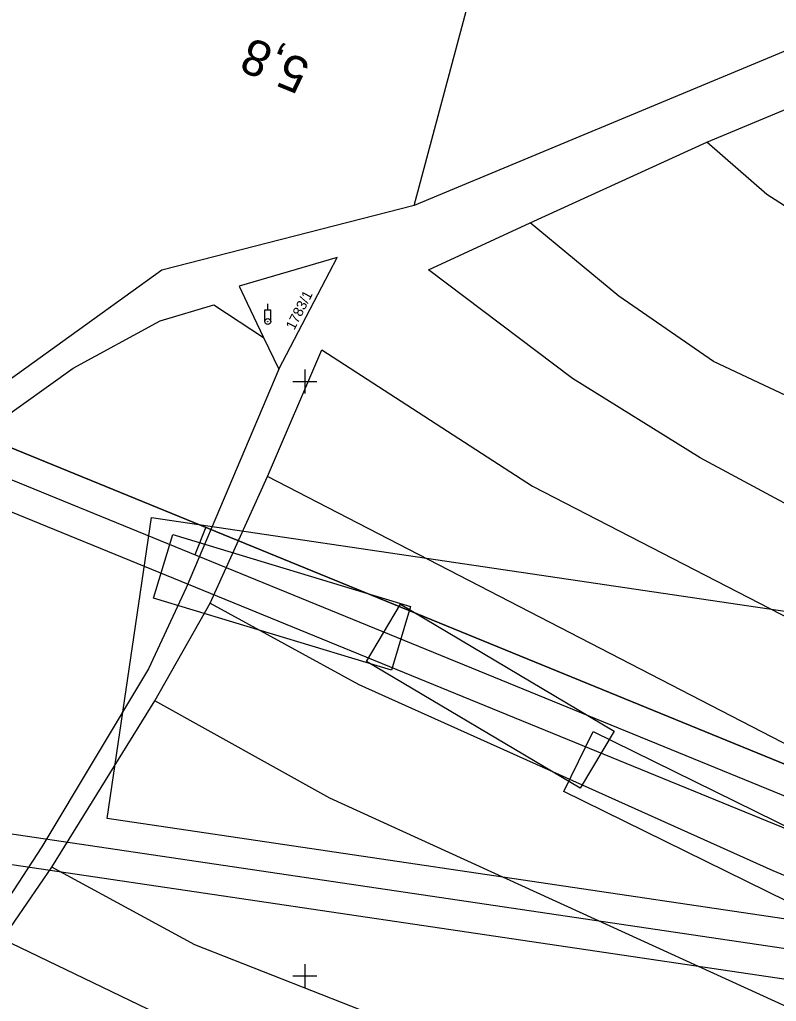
# Model space of a CAD drawing. Extents: x -779302 to -774398, y -1144902 to -1142831.
# Drawn here: x -776048 to -775920.6, y -1144504.3 to -1144339.1 of the extents above; entities that cross this region are included whole.
import ezdxf

# ---------------------------------------------------------------- set-up
doc = ezdxf.new("R2010")
doc.units = 0
for name, color, linetype in [('hektosit - Vrstva 5', 7, 'Continuous'), ('Hranice parcel', 7, 'Continuous'), ('Parcelní čísla', 7, 'Continuous'), ('Poz předměty', 7, 'Continuous'), ('Vrstva 1', 7, 'Continuous'), ('Vrstva 21', 7, 'Continuous'), ('zjednodus_g_situ-seda - Vrstva 7', 7, 'Continuous')]:
    doc.layers.add(name, color=color, linetype=linetype)

msp = doc.modelspace()

# ---------------------------------------------------------------- linework, layer by layer
at = {"layer": 'hektosit - Vrstva 5'}
for p, q in [((-776000, -1144398), (-776000, -1144402)), ((-776002, -1144400), (-775998, -1144400)), ((-776000, -1144498), (-776000, -1144502)), ((-776002, -1144500), (-775998, -1144500))]:
    msp.add_line(p, q, dxfattribs=at)
at = {"layer": 'Hranice parcel'}
for p, q in [((-775981.59, -1144370.37), (-775971.9, -1144334.14)), ((-775932.33, -1144359.71), (-775901.49, -1144346.83)), ((-775962.06, -1144373.31), (-775932.33, -1144359.71)), ((-776006.94, -1144392.58), (-776004.38, -1144397.9)), ((-776015.92, -1144437.31), (-776006.3, -1144415.96)), ((-776025.28, -1144453.72), (-776015.92, -1144437.31)), ((-776042.6, -1144481.72), (-776025.28, -1144453.72))]:
    msp.add_line(p, q, dxfattribs=at)
for points in [[(-775981.59, -1144370.37), (-776024.08, -1144381.29), (-776074.15, -1144417.28), (-776118.18, -1144455.2), (-776112.29, -1144427.95), (-776110.57, -1144410.43), (-776116.98, -1144391.49), (-776118.42, -1144369.14), (-776117.19, -1144356.92), (-776108.4, -1144333.55), (-776104.65, -1144302.9)], [(-775872.73, -1144323.39), (-775899.66, -1144336.3), (-775981.59, -1144370.37)], [(-775530.47, -1144538.25), (-775614.03, -1144501.05), (-775693.38, -1144468.4), (-775807.58, -1144424.84), (-775855.95, -1144404.65), (-775905.53, -1144379.22), (-775922.22, -1144368.54), (-775932.33, -1144359.71)], [(-775542.63, -1144574.58), (-775653.03, -1144527.81), (-775735.37, -1144496.15), (-775832.43, -1144458.14), (-775905.87, -1144427.65), (-775933.46, -1144412.85), (-775954.92, -1144399.49), (-775979.21, -1144381.19), (-775962.06, -1144373.31)], [(-775539.64, -1144560.59), (-775607.18, -1144531.04), (-775681.45, -1144500.07), (-775736.49, -1144478.85), (-775842.73, -1144435.95), (-775901.97, -1144410.38), (-775931.23, -1144396.62), (-775947.17, -1144385.66), (-775962.06, -1144373.31)], [(-776004.38, -1144397.9), (-775997.13, -1144384.09), (-775994.54, -1144379.16), (-776011.07, -1144383.98), (-776009.7, -1144386.83), (-776006.94, -1144392.58)], [(-776140.32, -1144483.93), (-776132.59, -1144479.84), (-776132.08, -1144479.31), (-776087.91, -1144434.59), (-776064.78, -1144416.16), (-776038.99, -1144397.74), (-776024.35, -1144389.78), (-776015.3, -1144387.11), (-776006.94, -1144392.58)], [(-776006.3, -1144415.96), (-775997.16, -1144394.67), (-775961.7, -1144417.58), (-775901.69, -1144448.49), (-775715.04, -1144521.12), (-775624.37, -1144557.21), (-775558.78, -1144584.42)], [(-776004.38, -1144397.9), (-776019.96, -1144434.72), (-776026.35, -1144448.31), (-776044.3, -1144478.3), (-776064.98, -1144509.94)], [(-775779.42, -1144517.15), (-775844.51, -1144491.07), (-775909.48, -1144465.96), (-776006.3, -1144415.96)], [(-776015.92, -1144437.31), (-775990.94, -1144450.98), (-775921.21, -1144482.29), (-775822.27, -1144523.43), (-775786.84, -1144536.56)], [(-775621.73, -1144622.39), (-775655.13, -1144606.89), (-775692.28, -1144592.24), (-775753.33, -1144574.87), (-775878.82, -1144523.5), (-775995.79, -1144470.11), (-776025.28, -1144453.72)], [(-775672.58, -1144652.96), (-775749.19, -1144620.04), (-775837.88, -1144583.47), (-775917.7, -1144549.4), (-775955.24, -1144534.11), (-776014.21, -1144511.49), (-776050.88, -1144493.84), (-776042.6, -1144481.72)], [(-775650.49, -1144639.68), (-775711.28, -1144614.58), (-775803.63, -1144580.65), (-775882.53, -1144548.18), (-775952.86, -1144520.57), (-776018.54, -1144494.77), (-776042.6, -1144481.72)]]:
    msp.add_lwpolyline(points, dxfattribs=at)
at = {"layer": 'Poz předměty'}
for p, q in [((-776006.75, -1144387.91), (-776005.75, -1144387.91)), ((-776006.75, -1144389.91), (-776006.75, -1144387.91)), ((-776006.25, -1144387.91), (-776006.25, -1144386.91)), ((-776005.75, -1144389.91), (-776005.75, -1144387.91))]:
    msp.add_line(p, q, dxfattribs=at)
for radius in [0.5, 0.0303]:
    msp.add_circle((-776006.25, -1144389.91), radius, dxfattribs=at)
at = {"layer": 'Vrstva 1'}
msp.add_line((-776016.65, -1144424.52), (-776018.54, -1144429.14), dxfattribs=at)
for points in [[(-775713.68, -1144238.31), (-776879.99, -1143761.57), (-776992.36, -1144036.48), (-775826.05, -1144513.22)], [(-775828.78, -1144506.7), (-776985.84, -1144033.74), (-776877.25, -1143768.09), (-775720.2, -1144241.05)], [(-775726.71, -1144243.78), (-776684.76, -1143852.17), (-776789.57, -1144108.58), (-775831.52, -1144500.19)], [(-775831.52, -1144500.19), (-776789.57, -1144108.58), (-776684.76, -1143852.17), (-775726.71, -1144243.78)], [(-774799.29, -1144366.04), (-776045.7, -1144181.56), (-776089.18, -1144475.34), (-774842.77, -1144659.83)], [(-774846.98, -1144654.15), (-776083.5, -1144471.13), (-776041.48, -1144187.23), (-774804.97, -1144370.25)]]:
    msp.add_lwpolyline(points, close=True, dxfattribs=at)
at = {"layer": 'Vrstva 21'}
for points in [[(-775877.43, -1144444.82), (-775884.93, -1144495.48), (-776033.31, -1144473.51), (-776025.81, -1144422.86)], [(-776025.47, -1144436.46), (-776022.23, -1144425.74), (-775982.2, -1144437.86), (-775985.44, -1144448.57)], [(-775989.63, -1144447.1), (-775983.92, -1144437.47), (-775947.93, -1144458.8), (-775953.64, -1144468.43)], [(-775956.39, -1144468.95), (-775951.45, -1144458.9), (-775913.91, -1144477.35), (-775918.85, -1144487.4)]]:
    msp.add_lwpolyline(points, close=True, dxfattribs=at)

# ---------------------------------------------------------------- texts
at = {"layer": 'Parcelní čísla'}
msp.add_text('1783/1', height=1.7, rotation=63, dxfattribs=at).set_placement((-776001.79, -1144391.47))
at = {"layer": 'zjednodus_g_situ-seda - Vrstva 7'}
msp.add_text('5,8', height=6, rotation=157.7193, dxfattribs=at).set_placement((-775998.8, -1144346.22))

doc.saveas('drawing.dxf')
